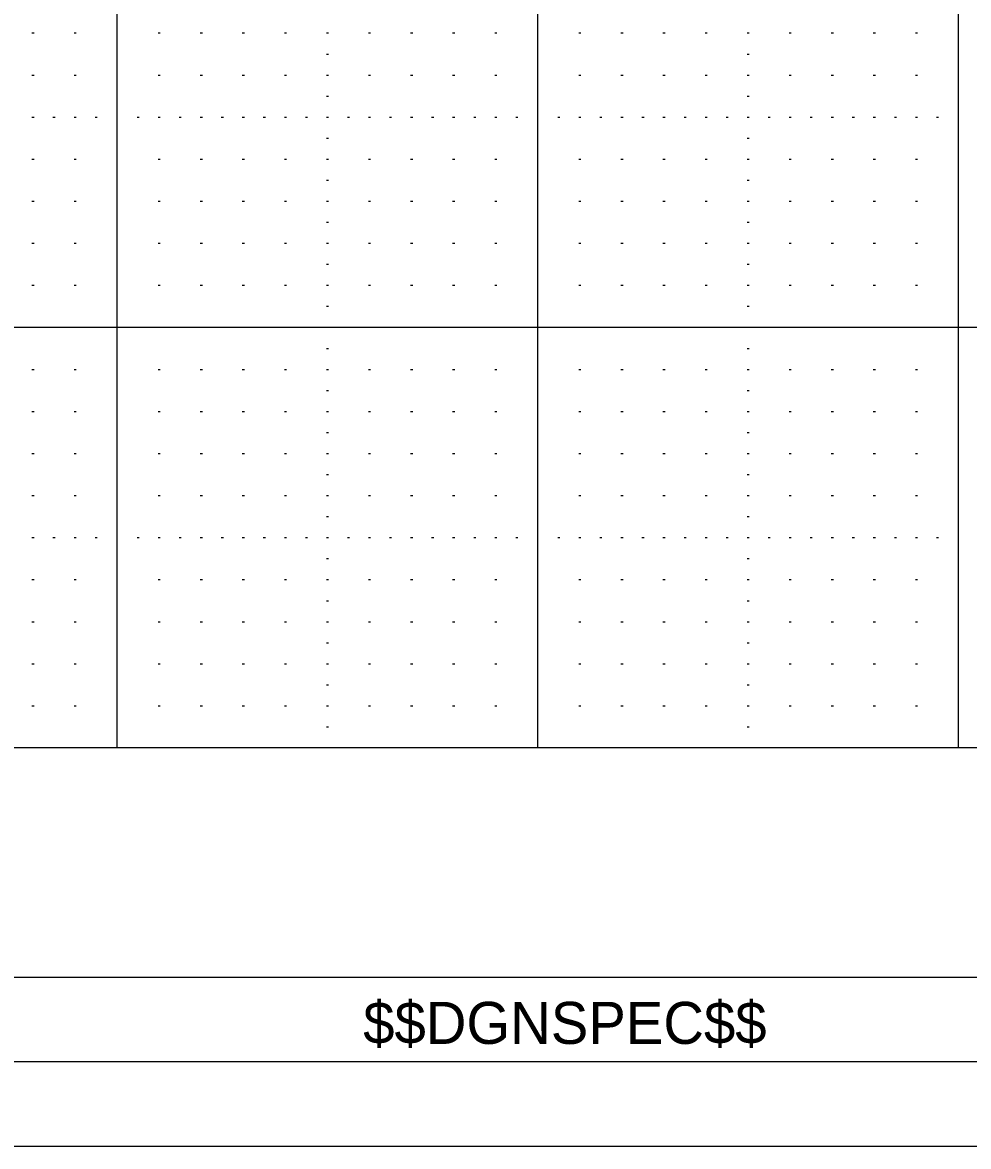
# Model space of a CAD drawing. Extents: x -3.6 to 32.1, y -0.4 to 20.9.
# Drawn here: x 27.583 to 29.832, y -0.403 to 2.27 of the extents above; entities that cross this region are included whole.
import ezdxf

# ---------------------------------------------------------------- set-up
doc = ezdxf.new("R2010")
doc.units = 0
for name, color, linetype in [('Level 1', 7, 'Continuous'), ('Level 37', 7, 'Continuous'), ('Level 4', 7, 'Continuous'), ('Level 48', 7, 'Continuous'), ('Level 5', 7, 'Continuous'), ('Level 63', 7, 'Continuous'), ('Level 63 Full', 7, 'Continuous')]:
    doc.layers.add(name, color=color, linetype=linetype)

msp = doc.modelspace()

# ---------------------------------------------------------------- linework, layer by layer
at = {"layer": 'Level 1'}
msp.add_line((31.617, -0.001), (-0.001, -0.001), dxfattribs=at)
at = {"layer": 'Level 37'}
msp.add_lwpolyline([(0.808, 9.545), (30.808, 9.545), (30.808, 0.545), (0.808, 0.545)], close=True, dxfattribs=at)
at = {"layer": 'Level 4'}
for p, q in [((27.808, 0.545), (27.808, 9.545)), ((28.808, 0.545), (28.808, 9.545)), ((29.808, 0.545), (29.808, 9.545)), ((31.617, 1.545), (-0.001, 1.545)), ((31.617, 0.545), (-0.001, 0.545))]:
    msp.add_line(p, q, dxfattribs=at)
at = {"layer": 'Level 5'}
for p, q in [((27.6055, 2.245), (27.6105, 2.245)), ((27.7055, 2.245), (27.7105, 2.245)), ((27.9055, 2.245), (27.9105, 2.245)), ((28.0055, 2.245), (28.0105, 2.245)), ((28.1055, 2.245), (28.1105, 2.245)), ((28.2055, 2.245), (28.2105, 2.245)), ((28.3055, 2.245), (28.3105, 2.245)), ((28.4055, 2.245), (28.4105, 2.245)), ((28.5055, 2.245), (28.5105, 2.245)), ((28.6055, 2.245), (28.6105, 2.245)), ((28.7055, 2.245), (28.7105, 2.245)), ((28.9055, 2.245), (28.9105, 2.245)), ((29.0055, 2.245), (29.0105, 2.245)), ((29.1055, 2.245), (29.1105, 2.245)), ((29.2055, 2.245), (29.2105, 2.245)), ((29.3055, 2.245), (29.3105, 2.245)), ((29.4055, 2.245), (29.4105, 2.245)), ((29.5055, 2.245), (29.5105, 2.245)), ((29.6055, 2.245), (29.6105, 2.245)), ((29.7055, 2.245), (29.7105, 2.245)), ((28.3055, 2.195), (28.3105, 2.195)), ((29.3055, 2.195), (29.3105, 2.195)), ((27.6055, 2.145), (27.6105, 2.145)), ((27.7055, 2.145), (27.7105, 2.145)), ((27.9055, 2.145), (27.9105, 2.145)), ((28.0055, 2.145), (28.0105, 2.145)), ((28.1055, 2.145), (28.1105, 2.145)), ((28.2055, 2.145), (28.2105, 2.145)), ((28.3055, 2.145), (28.3105, 2.145)), ((28.4055, 2.145), (28.4105, 2.145)), ((28.5055, 2.145), (28.5105, 2.145)), ((28.6055, 2.145), (28.6105, 2.145)), ((28.7055, 2.145), (28.7105, 2.145)), ((28.9055, 2.145), (28.9105, 2.145)), ((29.0055, 2.145), (29.0105, 2.145)), ((29.1055, 2.145), (29.1105, 2.145)), ((29.2055, 2.145), (29.2105, 2.145)), ((29.3055, 2.145), (29.3105, 2.145)), ((29.4055, 2.145), (29.4105, 2.145)), ((29.5055, 2.145), (29.5105, 2.145)), ((29.6055, 2.145), (29.6105, 2.145)), ((29.7055, 2.145), (29.7105, 2.145)), ((28.3055, 2.095), (28.3105, 2.095)), ((29.3055, 2.095), (29.3105, 2.095)), ((27.6055, 2.045), (27.6105, 2.045)), ((27.6555, 2.045), (27.6605, 2.045)), ((27.7055, 2.045), (27.7105, 2.045)), ((27.7555, 2.045), (27.7605, 2.045)), ((27.8555, 2.045), (27.8605, 2.045)), ((27.9055, 2.045), (27.9105, 2.045)), ((27.9555, 2.045), (27.9605, 2.045)), ((28.0055, 2.045), (28.0105, 2.045)), ((28.0555, 2.045), (28.0605, 2.045)), ((28.1055, 2.045), (28.1105, 2.045)), ((28.1555, 2.045), (28.1605, 2.045)), ((28.2055, 2.045), (28.2105, 2.045)), ((28.2555, 2.045), (28.2605, 2.045)), ((28.3055, 2.045), (28.3105, 2.045)), ((28.3555, 2.045), (28.3605, 2.045)), ((28.4055, 2.045), (28.4105, 2.045)), ((28.4555, 2.045), (28.4605, 2.045)), ((28.5055, 2.045), (28.5105, 2.045)), ((28.5555, 2.045), (28.5605, 2.045)), ((28.6055, 2.045), (28.6105, 2.045)), ((28.6555, 2.045), (28.6605, 2.045)), ((28.7055, 2.045), (28.7105, 2.045)), ((28.7555, 2.045), (28.7605, 2.045)), ((28.8555, 2.045), (28.8605, 2.045)), ((28.9055, 2.045), (28.9105, 2.045)), ((28.9555, 2.045), (28.9605, 2.045)), ((29.0055, 2.045), (29.0105, 2.045)), ((29.0555, 2.045), (29.0605, 2.045)), ((29.1055, 2.045), (29.1105, 2.045)), ((29.1555, 2.045), (29.1605, 2.045)), ((29.2055, 2.045), (29.2105, 2.045)), ((29.2555, 2.045), (29.2605, 2.045)), ((29.3055, 2.045), (29.3105, 2.045)), ((29.3555, 2.045), (29.3605, 2.045)), ((29.4055, 2.045), (29.4105, 2.045)), ((29.4555, 2.045), (29.4605, 2.045)), ((29.5055, 2.045), (29.5105, 2.045)), ((29.5555, 2.045), (29.5605, 2.045)), ((29.6055, 2.045), (29.6105, 2.045)), ((29.6555, 2.045), (29.6605, 2.045)), ((29.7055, 2.045), (29.7105, 2.045)), ((29.7555, 2.045), (29.7605, 2.045)), ((28.3055, 1.995), (28.3105, 1.995)), ((29.3055, 1.995), (29.3105, 1.995)), ((27.6055, 1.945), (27.6105, 1.945)), ((27.7055, 1.945), (27.7105, 1.945)), ((27.9055, 1.945), (27.9105, 1.945)), ((28.0055, 1.945), (28.0105, 1.945)), ((28.1055, 1.945), (28.1105, 1.945)), ((28.2055, 1.945), (28.2105, 1.945)), ((28.3055, 1.945), (28.3105, 1.945)), ((28.4055, 1.945), (28.4105, 1.945)), ((28.5055, 1.945), (28.5105, 1.945)), ((28.6055, 1.945), (28.6105, 1.945)), ((28.7055, 1.945), (28.7105, 1.945)), ((28.9055, 1.945), (28.9105, 1.945)), ((29.0055, 1.945), (29.0105, 1.945)), ((29.1055, 1.945), (29.1105, 1.945)), ((29.2055, 1.945), (29.2105, 1.945)), ((29.3055, 1.945), (29.3105, 1.945)), ((29.4055, 1.945), (29.4105, 1.945)), ((29.5055, 1.945), (29.5105, 1.945)), ((29.6055, 1.945), (29.6105, 1.945)), ((29.7055, 1.945), (29.7105, 1.945)), ((28.3055, 1.895), (28.3105, 1.895)), ((29.3055, 1.895), (29.3105, 1.895)), ((27.6055, 1.845), (27.6105, 1.845)), ((27.7055, 1.845), (27.7105, 1.845)), ((27.9055, 1.845), (27.9105, 1.845)), ((28.0055, 1.845), (28.0105, 1.845)), ((28.1055, 1.845), (28.1105, 1.845)), ((28.2055, 1.845), (28.2105, 1.845)), ((28.3055, 1.845), (28.3105, 1.845)), ((28.4055, 1.845), (28.4105, 1.845)), ((28.5055, 1.845), (28.5105, 1.845)), ((28.6055, 1.845), (28.6105, 1.845)), ((28.7055, 1.845), (28.7105, 1.845)), ((28.9055, 1.845), (28.9105, 1.845)), ((29.0055, 1.845), (29.0105, 1.845)), ((29.1055, 1.845), (29.1105, 1.845)), ((29.2055, 1.845), (29.2105, 1.845)), ((29.3055, 1.845), (29.3105, 1.845)), ((29.4055, 1.845), (29.4105, 1.845)), ((29.5055, 1.845), (29.5105, 1.845)), ((29.6055, 1.845), (29.6105, 1.845)), ((29.7055, 1.845), (29.7105, 1.845)), ((28.3055, 1.795), (28.3105, 1.795)), ((29.3055, 1.795), (29.3105, 1.795)), ((27.6055, 1.745), (27.6105, 1.745)), ((27.7055, 1.745), (27.7105, 1.745)), ((27.9055, 1.745), (27.9105, 1.745)), ((28.0055, 1.745), (28.0105, 1.745)), ((28.1055, 1.745), (28.1105, 1.745)), ((28.2055, 1.745), (28.2105, 1.745)), ((28.3055, 1.745), (28.3105, 1.745)), ((28.4055, 1.745), (28.4105, 1.745)), ((28.5055, 1.745), (28.5105, 1.745)), ((28.6055, 1.745), (28.6105, 1.745)), ((28.7055, 1.745), (28.7105, 1.745)), ((28.9055, 1.745), (28.9105, 1.745)), ((29.0055, 1.745), (29.0105, 1.745)), ((29.1055, 1.745), (29.1105, 1.745)), ((29.2055, 1.745), (29.2105, 1.745)), ((29.3055, 1.745), (29.3105, 1.745)), ((29.4055, 1.745), (29.4105, 1.745)), ((29.5055, 1.745), (29.5105, 1.745)), ((29.6055, 1.745), (29.6105, 1.745)), ((29.7055, 1.745), (29.7105, 1.745)), ((28.3055, 1.695), (28.3105, 1.695)), ((29.3055, 1.695), (29.3105, 1.695)), ((27.6055, 1.645), (27.6105, 1.645)), ((27.7055, 1.645), (27.7105, 1.645)), ((27.9055, 1.645), (27.9105, 1.645)), ((28.0055, 1.645), (28.0105, 1.645)), ((28.1055, 1.645), (28.1105, 1.645)), ((28.2055, 1.645), (28.2105, 1.645)), ((28.3055, 1.645), (28.3105, 1.645)), ((28.4055, 1.645), (28.4105, 1.645)), ((28.5055, 1.645), (28.5105, 1.645)), ((28.6055, 1.645), (28.6105, 1.645)), ((28.7055, 1.645), (28.7105, 1.645)), ((28.9055, 1.645), (28.9105, 1.645)), ((29.0055, 1.645), (29.0105, 1.645)), ((29.1055, 1.645), (29.1105, 1.645)), ((29.2055, 1.645), (29.2105, 1.645)), ((29.3055, 1.645), (29.3105, 1.645)), ((29.4055, 1.645), (29.4105, 1.645)), ((29.5055, 1.645), (29.5105, 1.645)), ((29.6055, 1.645), (29.6105, 1.645)), ((29.7055, 1.645), (29.7105, 1.645)), ((28.3055, 1.595), (28.3105, 1.595)), ((29.3055, 1.595), (29.3105, 1.595)), ((28.3055, 1.495), (28.3105, 1.495)), ((29.3055, 1.495), (29.3105, 1.495)), ((27.6055, 1.445), (27.6105, 1.445)), ((27.7055, 1.445), (27.7105, 1.445)), ((27.9055, 1.445), (27.9105, 1.445)), ((28.0055, 1.445), (28.0105, 1.445)), ((28.1055, 1.445), (28.1105, 1.445)), ((28.2055, 1.445), (28.2105, 1.445)), ((28.3055, 1.445), (28.3105, 1.445)), ((28.4055, 1.445), (28.4105, 1.445)), ((28.5055, 1.445), (28.5105, 1.445)), ((28.6055, 1.445), (28.6105, 1.445)), ((28.7055, 1.445), (28.7105, 1.445)), ((28.9055, 1.445), (28.9105, 1.445)), ((29.0055, 1.445), (29.0105, 1.445)), ((29.1055, 1.445), (29.1105, 1.445)), ((29.2055, 1.445), (29.2105, 1.445)), ((29.3055, 1.445), (29.3105, 1.445)), ((29.4055, 1.445), (29.4105, 1.445)), ((29.5055, 1.445), (29.5105, 1.445)), ((29.6055, 1.445), (29.6105, 1.445)), ((29.7055, 1.445), (29.7105, 1.445)), ((28.3055, 1.395), (28.3105, 1.395)), ((29.3055, 1.395), (29.3105, 1.395)), ((27.6055, 1.345), (27.6105, 1.345)), ((27.7055, 1.345), (27.7105, 1.345)), ((27.9055, 1.345), (27.9105, 1.345)), ((28.0055, 1.345), (28.0105, 1.345)), ((28.1055, 1.345), (28.1105, 1.345)), ((28.2055, 1.345), (28.2105, 1.345)), ((28.3055, 1.345), (28.3105, 1.345)), ((28.4055, 1.345), (28.4105, 1.345)), ((28.5055, 1.345), (28.5105, 1.345)), ((28.6055, 1.345), (28.6105, 1.345)), ((28.7055, 1.345), (28.7105, 1.345)), ((28.9055, 1.345), (28.9105, 1.345)), ((29.0055, 1.345), (29.0105, 1.345)), ((29.1055, 1.345), (29.1105, 1.345)), ((29.2055, 1.345), (29.2105, 1.345)), ((29.3055, 1.345), (29.3105, 1.345)), ((29.4055, 1.345), (29.4105, 1.345)), ((29.5055, 1.345), (29.5105, 1.345)), ((29.6055, 1.345), (29.6105, 1.345)), ((29.7055, 1.345), (29.7105, 1.345)), ((28.3055, 1.295), (28.3105, 1.295)), ((29.3055, 1.295), (29.3105, 1.295)), ((27.6055, 1.245), (27.6105, 1.245)), ((27.7055, 1.245), (27.7105, 1.245)), ((27.9055, 1.245), (27.9105, 1.245)), ((28.0055, 1.245), (28.0105, 1.245)), ((28.1055, 1.245), (28.1105, 1.245)), ((28.2055, 1.245), (28.2105, 1.245)), ((28.3055, 1.245), (28.3105, 1.245)), ((28.4055, 1.245), (28.4105, 1.245)), ((28.5055, 1.245), (28.5105, 1.245)), ((28.6055, 1.245), (28.6105, 1.245)), ((28.7055, 1.245), (28.7105, 1.245)), ((28.9055, 1.245), (28.9105, 1.245)), ((29.0055, 1.245), (29.0105, 1.245)), ((29.1055, 1.245), (29.1105, 1.245)), ((29.2055, 1.245), (29.2105, 1.245)), ((29.3055, 1.245), (29.3105, 1.245)), ((29.4055, 1.245), (29.4105, 1.245)), ((29.5055, 1.245), (29.5105, 1.245)), ((29.6055, 1.245), (29.6105, 1.245)), ((29.7055, 1.245), (29.7105, 1.245)), ((28.3055, 1.195), (28.3105, 1.195)), ((29.3055, 1.195), (29.3105, 1.195)), ((27.6055, 1.145), (27.6105, 1.145)), ((27.7055, 1.145), (27.7105, 1.145)), ((27.9055, 1.145), (27.9105, 1.145)), ((28.0055, 1.145), (28.0105, 1.145)), ((28.1055, 1.145), (28.1105, 1.145)), ((28.2055, 1.145), (28.2105, 1.145)), ((28.3055, 1.145), (28.3105, 1.145)), ((28.4055, 1.145), (28.4105, 1.145)), ((28.5055, 1.145), (28.5105, 1.145)), ((28.6055, 1.145), (28.6105, 1.145)), ((28.7055, 1.145), (28.7105, 1.145)), ((28.9055, 1.145), (28.9105, 1.145)), ((29.0055, 1.145), (29.0105, 1.145)), ((29.1055, 1.145), (29.1105, 1.145)), ((29.2055, 1.145), (29.2105, 1.145)), ((29.3055, 1.145), (29.3105, 1.145)), ((29.4055, 1.145), (29.4105, 1.145)), ((29.5055, 1.145), (29.5105, 1.145)), ((29.6055, 1.145), (29.6105, 1.145)), ((29.7055, 1.145), (29.7105, 1.145)), ((28.3055, 1.095), (28.3105, 1.095)), ((29.3055, 1.095), (29.3105, 1.095)), ((27.6055, 1.045), (27.6105, 1.045)), ((27.6555, 1.045), (27.6605, 1.045)), ((27.7055, 1.045), (27.7105, 1.045)), ((27.7555, 1.045), (27.7605, 1.045)), ((27.8555, 1.045), (27.8605, 1.045)), ((27.9055, 1.045), (27.9105, 1.045)), ((27.9555, 1.045), (27.9605, 1.045)), ((28.0055, 1.045), (28.0105, 1.045)), ((28.0555, 1.045), (28.0605, 1.045)), ((28.1055, 1.045), (28.1105, 1.045)), ((28.1555, 1.045), (28.1605, 1.045)), ((28.2055, 1.045), (28.2105, 1.045)), ((28.2555, 1.045), (28.2605, 1.045)), ((28.3055, 1.045), (28.3105, 1.045)), ((28.3555, 1.045), (28.3605, 1.045)), ((28.4055, 1.045), (28.4105, 1.045)), ((28.4555, 1.045), (28.4605, 1.045)), ((28.5055, 1.045), (28.5105, 1.045)), ((28.5555, 1.045), (28.5605, 1.045)), ((28.6055, 1.045), (28.6105, 1.045)), ((28.6555, 1.045), (28.6605, 1.045)), ((28.7055, 1.045), (28.7105, 1.045)), ((28.7555, 1.045), (28.7605, 1.045)), ((28.8555, 1.045), (28.8605, 1.045)), ((28.9055, 1.045), (28.9105, 1.045)), ((28.9555, 1.045), (28.9605, 1.045)), ((29.0055, 1.045), (29.0105, 1.045)), ((29.0555, 1.045), (29.0605, 1.045)), ((29.1055, 1.045), (29.1105, 1.045)), ((29.1555, 1.045), (29.1605, 1.045)), ((29.2055, 1.045), (29.2105, 1.045)), ((29.2555, 1.045), (29.2605, 1.045)), ((29.3055, 1.045), (29.3105, 1.045)), ((29.3555, 1.045), (29.3605, 1.045)), ((29.4055, 1.045), (29.4105, 1.045)), ((29.4555, 1.045), (29.4605, 1.045)), ((29.5055, 1.045), (29.5105, 1.045)), ((29.5555, 1.045), (29.5605, 1.045)), ((29.6055, 1.045), (29.6105, 1.045)), ((29.6555, 1.045), (29.6605, 1.045)), ((29.7055, 1.045), (29.7105, 1.045)), ((29.7555, 1.045), (29.7605, 1.045)), ((28.3055, 0.995), (28.3105, 0.995)), ((29.3055, 0.995), (29.3105, 0.995)), ((27.6055, 0.945), (27.6105, 0.945)), ((27.7055, 0.945), (27.7105, 0.945)), ((27.9055, 0.945), (27.9105, 0.945)), ((28.0055, 0.945), (28.0105, 0.945)), ((28.1055, 0.945), (28.1105, 0.945)), ((28.2055, 0.945), (28.2105, 0.945)), ((28.3055, 0.945), (28.3105, 0.945)), ((28.4055, 0.945), (28.4105, 0.945)), ((28.5055, 0.945), (28.5105, 0.945)), ((28.6055, 0.945), (28.6105, 0.945)), ((28.7055, 0.945), (28.7105, 0.945)), ((28.9055, 0.945), (28.9105, 0.945)), ((29.0055, 0.945), (29.0105, 0.945)), ((29.1055, 0.945), (29.1105, 0.945)), ((29.2055, 0.945), (29.2105, 0.945)), ((29.3055, 0.945), (29.3105, 0.945)), ((29.4055, 0.945), (29.4105, 0.945)), ((29.5055, 0.945), (29.5105, 0.945)), ((29.6055, 0.945), (29.6105, 0.945)), ((29.7055, 0.945), (29.7105, 0.945)), ((28.3055, 0.895), (28.3105, 0.895)), ((29.3055, 0.895), (29.3105, 0.895)), ((27.6055, 0.845), (27.6105, 0.845)), ((27.7055, 0.845), (27.7105, 0.845)), ((27.9055, 0.845), (27.9105, 0.845)), ((28.0055, 0.845), (28.0105, 0.845)), ((28.1055, 0.845), (28.1105, 0.845)), ((28.2055, 0.845), (28.2105, 0.845)), ((28.3055, 0.845), (28.3105, 0.845)), ((28.4055, 0.845), (28.4105, 0.845)), ((28.5055, 0.845), (28.5105, 0.845)), ((28.6055, 0.845), (28.6105, 0.845)), ((28.7055, 0.845), (28.7105, 0.845)), ((28.9055, 0.845), (28.9105, 0.845)), ((29.0055, 0.845), (29.0105, 0.845)), ((29.1055, 0.845), (29.1105, 0.845)), ((29.2055, 0.845), (29.2105, 0.845)), ((29.3055, 0.845), (29.3105, 0.845)), ((29.4055, 0.845), (29.4105, 0.845)), ((29.5055, 0.845), (29.5105, 0.845)), ((29.6055, 0.845), (29.6105, 0.845)), ((29.7055, 0.845), (29.7105, 0.845)), ((28.3055, 0.795), (28.3105, 0.795)), ((29.3055, 0.795), (29.3105, 0.795)), ((27.6055, 0.745), (27.6105, 0.745)), ((27.7055, 0.745), (27.7105, 0.745)), ((27.9055, 0.745), (27.9105, 0.745)), ((28.0055, 0.745), (28.0105, 0.745)), ((28.1055, 0.745), (28.1105, 0.745)), ((28.2055, 0.745), (28.2105, 0.745)), ((28.3055, 0.745), (28.3105, 0.745)), ((28.4055, 0.745), (28.4105, 0.745)), ((28.5055, 0.745), (28.5105, 0.745)), ((28.6055, 0.745), (28.6105, 0.745)), ((28.7055, 0.745), (28.7105, 0.745)), ((28.9055, 0.745), (28.9105, 0.745)), ((29.0055, 0.745), (29.0105, 0.745)), ((29.1055, 0.745), (29.1105, 0.745)), ((29.2055, 0.745), (29.2105, 0.745)), ((29.3055, 0.745), (29.3105, 0.745)), ((29.4055, 0.745), (29.4105, 0.745)), ((29.5055, 0.745), (29.5105, 0.745)), ((29.6055, 0.745), (29.6105, 0.745)), ((29.7055, 0.745), (29.7105, 0.745)), ((28.3055, 0.695), (28.3105, 0.695)), ((29.3055, 0.695), (29.3105, 0.695)), ((27.6055, 0.645), (27.6105, 0.645)), ((27.7055, 0.645), (27.7105, 0.645)), ((27.9055, 0.645), (27.9105, 0.645)), ((28.0055, 0.645), (28.0105, 0.645)), ((28.1055, 0.645), (28.1105, 0.645)), ((28.2055, 0.645), (28.2105, 0.645)), ((28.3055, 0.645), (28.3105, 0.645)), ((28.4055, 0.645), (28.4105, 0.645)), ((28.5055, 0.645), (28.5105, 0.645)), ((28.6055, 0.645), (28.6105, 0.645)), ((28.7055, 0.645), (28.7105, 0.645)), ((28.9055, 0.645), (28.9105, 0.645)), ((29.0055, 0.645), (29.0105, 0.645)), ((29.1055, 0.645), (29.1105, 0.645)), ((29.2055, 0.645), (29.2105, 0.645)), ((29.3055, 0.645), (29.3105, 0.645)), ((29.4055, 0.645), (29.4105, 0.645)), ((29.5055, 0.645), (29.5105, 0.645)), ((29.6055, 0.645), (29.6105, 0.645)), ((29.7055, 0.645), (29.7105, 0.645)), ((28.3055, 0.595), (28.3105, 0.595)), ((29.3055, 0.595), (29.3105, 0.595))]:
    msp.add_line(p, q, dxfattribs=at)
at = {"layer": 'Level 63'}
msp.add_lwpolyline([(-1.263, -0.2005), (32.067, -0.2005), (32.067, 20.7465), (-1.263, 20.7465)], close=True, dxfattribs=at)
at = {"layer": 'Level 63 Full'}
msp.add_lwpolyline([(32.017, -0.403), (-3.583, -0.403), (-3.583, 20.947), (32.017, 20.947)], close=True, dxfattribs=at)

# ---------------------------------------------------------------- texts
at = {"layer": 'Level 48'}
msp.add_text('$$DGNSPEC$$', height=0.100002, dxfattribs=at).set_placement((28.3929, -0.159))

doc.saveas('drawing.dxf')
